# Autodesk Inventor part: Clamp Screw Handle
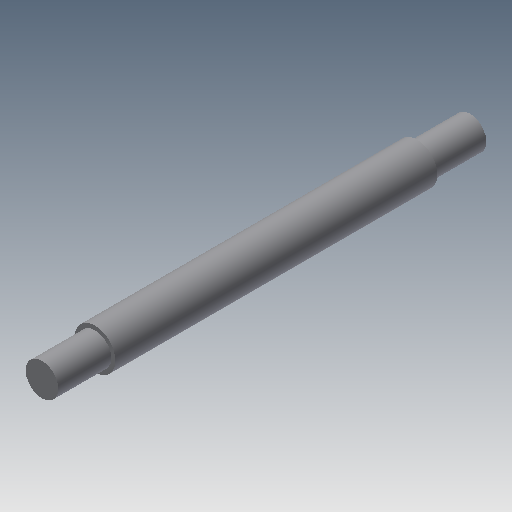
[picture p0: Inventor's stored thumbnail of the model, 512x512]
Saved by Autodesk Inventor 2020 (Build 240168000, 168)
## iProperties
Created: 2002-02
Part Number: Clamp Screw Handle
Document SubType Name: Modeling
Designer: ***
Density: 1 g/cm^3
Material: Generic
Mass: 7.51155 g
Surface Area: 32.9239 cm^2
Volume: 7.51155 cm^3
Appearance: Default
Control State: 0
Master: False
Checked Out: False
Shininess: 77.0
Length Units: 11269
Angle Units: 11279
Time Units: 11290
Mass Units: 11283
Length Display Precision: 3
Angle Display Precision: 2
Compacted: True
Density: 0.0
Volumn: 0.0
Area: 0.0
PropertySet Name: Model Information
Author: ***
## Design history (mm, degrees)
sketch "Sketch1"
  geometry: L1 (0, 105)-(4, 105); L2 (4, 105)-(4, 92); L3 (4, 92)-(5, 92); L4 (5, 92)-(5, 13); L5 (5, 13)-(4, 13); L6 (4, 13)-(4, 0); L7 (4, 0)-(0, 0); L8 (0, 0)-(0, 105)
  constraints: 16 end point, 5 parallel, 2 equal length, 1 collinear, 1 horizontal, 1 perpendicular
  dimensions: "d0" = 10 diameter of L4 L8; "d1" = 8 diameter of L2 L8; "d2" = 13 distance of L1.end L2.end; "d3" = 79 distance of L3.end L4.end
revolve "Revolution1" sketch "Sketch1" stored, may be unused: angle "d4" = 90 deg
body "Solid1"
